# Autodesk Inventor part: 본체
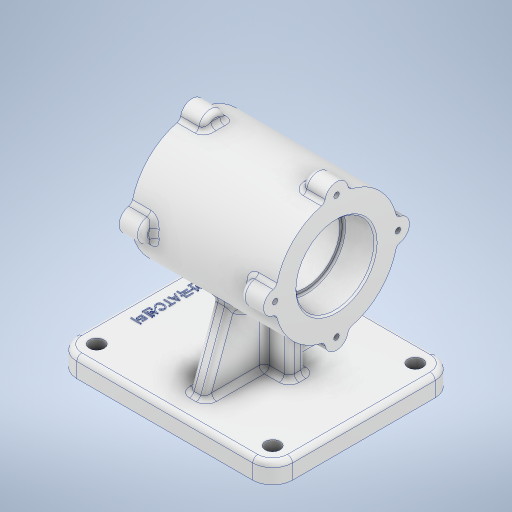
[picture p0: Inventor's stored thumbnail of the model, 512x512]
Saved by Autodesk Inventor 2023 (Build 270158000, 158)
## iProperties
Created: 2023-08
Part Number: 본체
Material: 알루미늄 6061
Document SubType Name: Modeling
Designer: asung
Mass: 1215.39 g
Surface Area: 796.917 cm^2
Volume: 450.145 cm^3
Density: 2.7 g/cm^3
Appearance: 알루미늄 - 평지
Author: asung
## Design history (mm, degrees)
sketch "스케치1"
  geometry: L1 (53, 55)-(-53, 55); L2 (-65, 43)-(-65, -43); L3 (-53, -55)-(53, -55); L4 (65, -43)-(65, 43); L5 (65, 55)-(-65, -55); L6 (-65, 55)-(65, -55); A1 r 12 centre (53, -43) between (53, -55) and (65, -43); A2 r 12 centre (53, 43) between (65, 43) and (53, 55); A3 r 12 centre (-53, 43) between (-53, 55) and (-65, 43); A4 r 12 centre (-53, -43) between (-65, -43) and (-53, -55); 1 further point
  constraints: 12 end point, 8 point on circle, 8 point on line, 8 tangent, 4 centre point, 3 equal radius, 2 midpoint, 2 parallel, 1 horizontal, 1 perpendicular
  dimensions: "d0" = 130 distance of L6.end L5.end; "d1" = 110 distance of L5.end L6.start; "d2" = 12 radius of A1
extrude "돌출1" new body sketch "스케치1" distance "d3" = 12; taper "d4" = 0 deg
fillet "모깎기1" dims "d5" = 3
sketch "스케치2"
  geometry: L1 (-62, -43)-(-62, 43) reference; L2 (53, -52)-(-53, -52) reference; L3 (62, 43)-(62, -43) reference; L4 (-53, 52)-(53, 52) reference; C1 r 4.5 at (-53, 43); C2 r 4.5 at (53, 43); C3 r 4.5 at (-53, -43); C4 r 4.5 at (53, -43); A1 r 9 centre (-53, 43) between (-53, 52) and (-62, 43) reference; A2 r 9 centre (-53, -43) between (-62, -43) and (-53, -52) reference; A3 r 9 centre (53, -43) between (53, -52) and (62, -43) reference; A4 r 9 centre (53, 43) between (62, 43) and (53, 52) reference; 1 further point
  constraints: 4 centre point, 4 coincident
  dimensions: "d6" = 9 diameter of C1; "d7" = 9 diameter of C2; "d8" = 9 diameter of C3; "d9" = 9 diameter of C4
extrude "돌출2" cut sketch "스케치2" distance "d10" = 12; taper "d11" = 0 deg
node "작업 평면3"
sketch "스케치3"
  geometry: L1 (-9, 12)-(95, 12) reference; L2 (98, 9)-(98, 0) reference; L3 (98, 0)-(-12, 0) reference; L4 (-12, 0)-(-12, 9) reference; L5 (43, 0)-(43, 82); C1 r 37 at (43, 82); A1 r 3 centre (-9, 9) between (-9, 12) and (-12, 9) reference; A2 r 3 centre (95, 9) between (98, 9) and (95, 12) reference
  constraints: 2 end point, 1 centre point, 1 coincident, 1 vertical
  dimensions: "d13" = 82 distance of L5.start L5.end; "d15" = 37 radius of C1
extrude "돌출3" join sketch "스케치3" stored distance "d16" = 87; taper "d17" = 0 deg
sketch "스케치4"
  geometry: C1 r 7 at (0, 37); C2 r 7 at (37, 0); C3 r 7 at (0, -37); C4 r 7 at (-37, 0); A1 r 37 centre (0, 0) between (0, 37) and (37, 0) reference; 1 further point
  constraints: 4 centre point, 4 point on circle
  dimensions: "d18" = 7 radius of C1; "d19" = 7 radius of C2; "d20" = 7 radius of C3; "d21" = 7 radius of C4
extrude "돌출4" join sketch "스케치4" distance "d22" = 14; taper "d23" = 0 deg
fillet "모깎기2" dims "d24" = 3
fillet "모깎기3" dims "d25" = 3
fillet "모깎기4" dims "d26" = 3
fillet "모깎기5" dims "d27" = 3
sketch "스케치5"
  geometry: A1 r 37 centre (43, 82) between (7.138, 72.896) and (33.896, 46.138) reference; A2 r 3 centre (33.158, 43.23) between (36.111, 43.761) and (33.896, 46.138) reference; A3 r 7 centre (43, 45) between (36.111, 43.761) and (49.889, 43.761) reference; A4 r 3 centre (52.842, 43.23) between (52.104, 46.138) and (49.889, 43.761) reference; A5 r 37 centre (43, 82) between (52.104, 46.138) and (78.862, 72.896) reference; A6 r 3 centre (81.77, 72.158) between (81.239, 75.111) and (78.862, 72.896) reference; A7 r 7 centre (80, 82) between (81.239, 75.111) and (81.239, 88.889) reference; A8 r 3 centre (81.77, 91.842) between (78.863, 91.104) and (81.239, 88.889) reference; A9 r 37 centre (43, 82) between (78.863, 91.104) and (52.104, 117.863) reference; A10 r 3 centre (52.842, 120.77) between (49.889, 120.239) and (52.104, 117.863) reference; A11 r 7 centre (43, 119) between (49.889, 120.239) and (36.111, 120.239) reference; A12 r 3 centre (33.158, 120.77) between (33.896, 117.863) and (36.111, 120.239) reference; A13 r 37 centre (43, 82) between (33.896, 117.863) and (7.137, 91.104) reference; A14 r 3 centre (4.23, 91.842) between (4.761, 88.889) and (7.137, 91.104) reference; A15 r 7 centre (6, 82) between (4.761, 88.889) and (4.761, 75.111) reference; A16 r 3 centre (4.23, 72.158) between (7.138, 72.896) and (4.761, 75.111) reference; 1 further point
hole "구멍1" sketch "스케치5" at (43, 82) diameter "d28" = 42; stored, may be unused: countersink angle "d32" = 90 deg, drill point angle "d34" = 0 deg; dims "d29" = 10, "d30" = 47, "d31" = 19, "d33" = 87
sketch "스케치6"
  geometry: C1 r 37 at (0, 0) reference; 2 further points
  constraints: 1 coincident
hole "구멍2" sketch "스케치6" at (0, 0) diameter "d35" = 42; stored, may be unused: countersink angle "d39" = 90 deg, drill point angle "d41" = 0 deg; dims "d36" = 6, "d37" = 47, "d38" = 19, "d40" = 87
node "작업 평면4"
sketch "스케치7"
  geometry: C1 r 23.5 at (43, 82) reference; A1 r 37 centre (43, 82) between (7.138, 72.896) and (33.896, 46.138) reference; A2 r 3 centre (33.158, 43.23) between (36.111, 43.761) and (33.896, 46.138) reference; A3 r 7 centre (43, 45) between (36.111, 43.761) and (49.889, 43.761) reference; A4 r 3 centre (52.842, 43.23) between (52.104, 46.138) and (49.889, 43.761) reference; A5 r 37 centre (43, 82) between (52.104, 46.138) and (78.862, 72.896) reference; A6 r 3 centre (81.77, 72.158) between (81.239, 75.111) and (78.862, 72.896) reference; A7 r 7 centre (80, 82) between (81.239, 75.111) and (81.239, 88.889) reference; A8 r 3 centre (81.77, 91.842) between (78.863, 91.104) and (81.239, 88.889) reference; A9 r 37 centre (43, 82) between (78.863, 91.104) and (52.104, 117.863) reference; A10 r 3 centre (52.842, 120.77) between (49.889, 120.239) and (52.104, 117.863) reference; A11 r 7 centre (43, 119) between (49.889, 120.239) and (36.111, 120.239) reference; A12 r 3 centre (33.158, 120.77) between (33.896, 117.863) and (36.111, 120.239) reference; A13 r 37 centre (43, 82) between (33.896, 117.863) and (7.137, 91.104) reference; A14 r 3 centre (4.23, 91.842) between (4.761, 88.889) and (7.137, 91.104) reference; A15 r 7 centre (6, 82) between (4.761, 88.889) and (4.761, 75.111) reference; A16 r 3 centre (4.23, 72.158) between (7.138, 72.896) and (4.761, 75.111) reference; 1 further point
hole "구멍3" sketch "스케치7" at (43, 119) diameter "d42" = 3.242; stored, may be unused: countersink angle "d46" = 90 deg, drill point angle "d48" = 118 deg; dims "d43" = 8, "d44" = 47, "d45" = 19, "d47" = 10
sketch "스케치8"
  geometry: L1 (-62, 43)-(-62, -43) reference; L2 (-53, -52)-(53, -52) reference; L3 (62, -43)-(62, 43) reference; L4 (53, 52)-(-53, 52) reference; L5 (-29.193, 84.957)-(10.807, 84.957); L6 (0, 0)-(5, 0); L7 (5, 0)-(-15, 0); L8 (-15, -5)-(25, -5); L9 (25, -5)-(25, 5); L10 (25, 5)-(-15, 5); L11 (-15, 5)-(-15, -5); L12 (-15, -5)-(25, 5); L13 (25, -5)-(-15, 5); C1 r 4.5 at (53, -43) reference; C2 r 4.5 at (-53, -43) reference; C3 r 4.5 at (53, 43) reference; C4 r 4.5 at (-53, 43) reference; A1 r 9 centre (-53, 43) between (-53, 52) and (-62, 43) reference; A2 r 9 centre (-53, -43) between (-62, -43) and (-53, -52) reference; A3 r 9 centre (53, -43) between (53, -52) and (62, -43) reference; A4 r 9 centre (53, 43) between (62, 43) and (53, 52) reference; 1 further point
  constraints: 18 end point, 4 horizontal, 2 coincident, 2 midpoint, 2 parallel, 1 perpendicular
  dimensions: "d52" = 40 distance of L5.start L5.end; "d53" = 5 distance of L6.start L6.end; "d54" = 20 distance of L7.start L7.end; "d56" = 40 distance of L10.end L9.end; "d57" = 10 distance of L9.end L8.end
extrude "돌출5" join sketch "스케치8" stored distance "d58" = 14; taper "d59" = 0 deg
sketch "스케치9"
  geometry: L1 (-9, 12)-(38, 12) reference; L2 (38, 12)-(38, 45.339) reference; L3 (48, 45.339)-(48, 12) reference; L4 (48, 12)-(95, 12) reference; L5 (98, 9)-(98, 0) reference; L6 (98, 0)-(-12, 0) reference; L7 (-12, 0)-(-12, 9) reference; L8 (84, 12)-(68.336, 55.036); L9 (2, 12)-(17.664, 55.036); C1 r 21 at (43, 82) reference; A1 r 3 centre (-9, 9) between (-9, 12) and (-12, 9) reference; A2 r 37 centre (43, 82) between (48, 45.339) and (38, 45.339) reference; A3 r 3 centre (95, 9) between (98, 9) and (95, 12) reference; 1 further point
  constraints: 4 end point, 2 point on circle, 2 point on line
  dimensions: "d62" = 110 deg angle of L8 L4; "d63" = 110 deg angle of L1 L9
  node "절단 모서리 투영3"
feature "리브1" dims "d64" = 1, "d65" = 10, "d66" = 0, "d67" = 0, "d68" = 1, "d69" = 1
feature "리브2" dims "d70" = 1, "d71" = 10, "d72" = 0, "d73" = 0, "d74" = 1, "d75" = 1
fillet "모깎기6" dims "d76" = 3
fillet "모깎기7" dims "d77" = 3
sketch "스케치10"
  geometry: L1 (-3, 36.716)-(-3, 8) reference; L2 (-3, 8)-(-12, 8) reference; L3 (-18, 2)-(-18, -2) reference; L4 (-12, -8)-(-3, -8) reference; L5 (-3, -8)-(-3, -36.716) reference; L6 (3, -43.101)-(7, -43.101) reference; L7 (13, -36.716)-(13, -8) reference; L8 (13, -8)-(22, -8) reference; L9 (28, -2)-(28, 2) reference; L10 (22, 8)-(13, 8) reference; L11 (13, 8)-(13, 36.716) reference; L12 (7, 43.101)-(3, 43.101) reference; L13 (53, 52)-(-53, 52) reference; L14 (-62, 43)-(-62, -43) reference; L15 (-53, -52)-(53, -52) reference; L16 (62, -43)-(62, 43) reference; L17 (-53, -55)-(53, -55) reference; L18 (53, 55)-(-53, 55) reference; L19 (5, -77)-(5, 77) reference; C1 r 4.5 at (53, -43) reference; C2 r 4.5 at (-53, -43) reference; C3 r 4.5 at (53, 43) reference; C4 r 4.5 at (-53, 43) reference; A1 r 6 centre (-12, 2) between (-12, 8) and (-18, 2) reference; A2 r 6 centre (-12, -2) between (-18, -2) and (-12, -8) reference; A3 r 6 centre (22, -2) between (22, -8) and (28, -2) reference; A4 r 6 centre (22, 2) between (28, 2) and (22, 8) reference; A5 r 9 centre (-53, 43) between (-53, 52) and (-62, 43) reference; A6 r 9 centre (-53, -43) between (-62, -43) and (-53, -52) reference; A7 r 9 centre (53, -43) between (53, -52) and (62, -43) reference; A8 r 9 centre (53, 43) between (62, 43) and (53, 52) reference; 2 further points
  constraints: 5 other
  dimensions: "d79" = 58 distance from line of L19 point (-53, 0); "d80" = 55 distance of L17.start point (-53, 0)
feature "엠보싱1" sketch "스케치10" dims "d0" = 130, "d1" = 110, "d2" = 12, "d81" = 0.5, "d82" = 0
chamfer "모따기1" distance "d83" = 1; stored, may be unused: second distance "d84" = 2, angle "d85" = 45 deg
node "작업 평면5"
fillet "모깎기8" dims "d86" = 1
sketch "스케치11"
  geometry: 1 further point
feature "Ӏ耀ӂ耀ӄ耀ӆ耀ӈ耀ӊ耀ӌ耀ӎ耀" dims "d0" = 130, "d1" = 110, "d2" = 12, "d3" = 12, "d4" = 0, "d5" = 3, "d6" = 9, "d7" = 9, "d8" = 9, "d9" = 9, "d10" = 12, "d11" = 0, "d12" = -70, "d13" = 82, "d15" = 37, "d16" = 87, "d17" = 0, "d18" = 7, "d19" = 7, "d20" = 7, "d21" = 7, "d22" = 14, "d23" = 0, "d24" = 3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
node "솔리드1"
mirror "미러1"
pattern_circular "원형 패턴1" dims angle "d50" = 360 deg
mirror "미러2"
node "투영된 루프1"
node "투영된 루프2"
node "투영된 루프3"
node "투영된 루프4"
node "절단 모서리 투영1"
node "절단 모서리 투영2"
node "절단 모서리 투영4"
feature "A9D066F2-1C7D-4E18-AEED-F7BC21143FA4" dims "d28" = 42, "d29" = 10, "d30" = 47, "d31" = 19, "d32" = 90 deg, "d33" = 87, "d34" = 0
